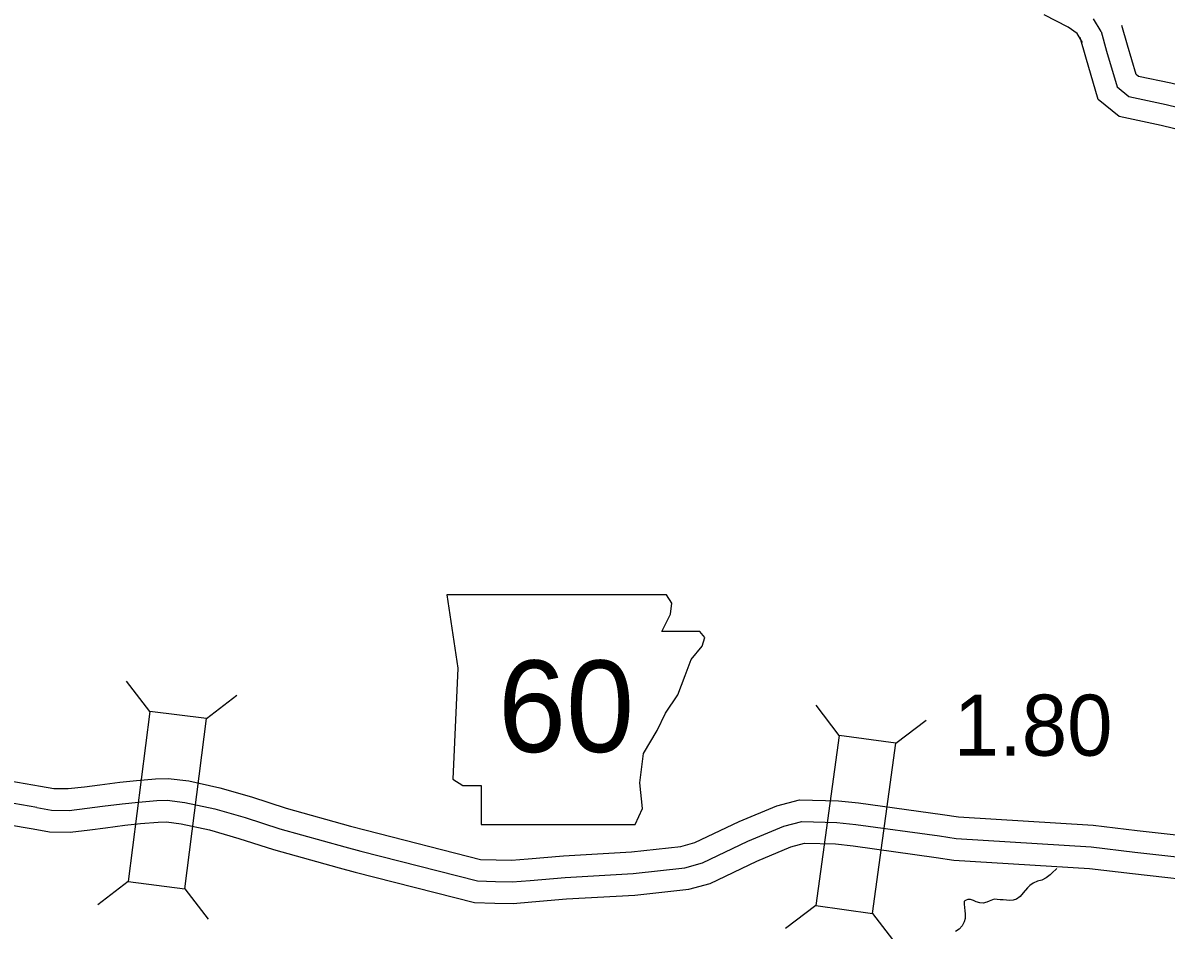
# Model space of a CAD drawing. Extents: x -83719 to 153526, y -11835 to 11446.
# Drawn here: x -2511.6 to -2247.8, y -714.3 to -505 of the extents above; entities that cross this region are included whole.
import ezdxf

# ---------------------------------------------------------------- set-up
doc = ezdxf.new("R2010")
doc.units = 0
for name, color, linetype in [('Level 10', 7, 'Continuous'), ('Level 20', 7, 'Continuous'), ('Level 21', 7, 'Continuous'), ('Level 58', 7, 'Continuous'), ('Level 59', 7, 'Continuous'), ('Level 9', 7, 'Continuous')]:
    doc.layers.add(name, color=color, linetype=linetype)

msp = doc.modelspace()

# ---------------------------------------------------------------- linework, layer by layer
at = {"layer": 'Level 10'}
for points in [[(-2267.06, -509.51), (-2268.32, -507.43), (-2270.35, -505.94), (-2275.89, -503.11)], [(-2135.16, -576.52), (-2141.29, -573.98), (-2181.87, -556.65), (-2184.87, -554.37), (-2191.3, -548.63), (-2202.4, -542.48), (-2211.06, -534.91), (-2216.36, -528), (-2222.14, -525.8), (-2230.15, -522.9), (-2246.67, -518.89), (-2254.14, -517.3), (-2254.7, -516.84), (-2256.69, -510.08), (-2257.97, -505.56)], [(-2138.99, -585.76), (-2145.17, -583.2), (-2186.94, -565.36), (-2191.24, -562.09), (-2197.12, -556.83), (-2208.18, -550.71), (-2218.38, -541.78), (-2222.56, -536.33), (-2225.62, -535.17), (-2233.04, -532.49), (-2248.89, -528.64), (-2258.59, -526.58), (-2263.42, -522.64), (-2266.3, -512.85), (-2267.59, -508.29)], [(-2728.32, -577.84), (-2728.29, -580.71), (-2727.84, -582.83), (-2720.37, -595.06), (-2719.66, -595.98), (-2718.27, -597.3), (-2689.7, -619.8), (-2686.51, -622.61), (-2684.68, -624.5), (-2683.87, -625.46), (-2658.55, -643.64), (-2631.11, -664.52), (-2627.02, -666.72), (-2625.87, -667.15), (-2609.49, -670.06), (-2587.64, -673.43), (-2562.55, -676.63), (-2560.66, -676.75), (-2547.94, -675.61), (-2544.34, -675.47), (-2519.99, -678.91), (-2507.5, -681.04)], [(-2737.85, -583.84), (-2737.27, -586.58), (-2728.62, -600.74), (-2727.11, -602.7), (-2724.81, -604.87), (-2696.1, -627.49), (-2693.42, -629.86), (-2692.09, -631.22), (-2690.7, -632.86), (-2664.5, -651.68), (-2636.54, -672.96), (-2631.17, -675.84), (-2628.54, -676.84), (-2611.12, -679.92), (-2589.03, -683.33), (-2563.53, -686.58), (-2560.55, -686.78), (-2547.3, -685.59), (-2544.85, -685.5), (-2521.53, -688.79), (-2509.19, -690.9)], [(-2507.47, -681.05), (-2504.44, -681.59), (-2501.14, -681.63), (-2497.37, -681.19), (-2493.81, -680.73), (-2489.19, -680.13), (-2485.34, -679.75), (-2480.94, -679.38), (-2478.02, -679.26), (-2473.3, -679.86), (-2466.08, -681.42), (-2458.78, -683.53), (-2450.82, -686.11), (-2435.93, -690.27), (-2432.35, -691.22), (-2405.93, -697.94), (-2402.37, -698.08), (-2398.8, -698.13), (-2394.93, -697.8), (-2386.81, -697.11), (-2371.15, -696.21), (-2359.74, -694.97), (-2356.48, -694.08), (-2346.31, -689.22), (-2337.57, -685.57), (-2332.38, -684.18), (-2323.37, -684.42), (-2318.71, -684.93), (-2299.36, -687.58), (-2295.66, -688.14), (-2264.57, -690.08), (-2254.41, -691.28), (-2235.83, -693.34)], [(-2509.22, -690.9), (-2505.39, -691.58), (-2500.62, -691.64), (-2496.14, -691.12), (-2492.52, -690.65), (-2488.04, -690.06), (-2484.44, -689.71), (-2480.32, -689.37), (-2478.45, -689.29), (-2475, -689.73), (-2468.53, -691.13), (-2461.71, -693.1), (-2453.71, -695.69), (-2438.56, -699.91), (-2434.87, -700.9), (-2407.36, -707.9), (-2402.63, -708.07), (-2398.46, -708.14), (-2394.08, -707.77), (-2386.1, -707.08), (-2370.32, -706.18), (-2357.87, -704.82), (-2352.98, -703.49), (-2342.22, -698.35), (-2334.34, -695.06), (-2331.19, -694.22), (-2324.05, -694.4), (-2319.94, -694.85), (-2300.79, -697.48), (-2296.72, -698.1), (-2265.47, -700.04), (-2255.55, -701.22), (-2236.53, -703.33)]]:
    msp.add_lwpolyline(points, dxfattribs=at)
at = {"layer": 'Level 20'}
for p, q in [((-2482.27, -663.8), (-2487.66, -656.84)), ((-2469.18, -665.47), (-2462.22, -660.08)), ((-2323.18, -669.38), (-2328.5, -662.37)), ((-2310.1, -671.17), (-2303.09, -665.85)), ((-2487.29, -703.08), (-2494.25, -708.46)), ((-2474.19, -704.75), (-2468.81, -711.71)), ((-2328.55, -708.61), (-2335.56, -713.93)), ((-2315.48, -710.4), (-2310.16, -717.41))]:
    msp.add_line(p, q, dxfattribs=at)
for points in [[(-2474.19, -704.75), (-2469.18, -665.47), (-2482.27, -663.8), (-2487.29, -703.08)], [(-2315.48, -710.4), (-2310.1, -671.17), (-2323.18, -669.38), (-2328.55, -708.61)]]:
    msp.add_lwpolyline(points, close=True, dxfattribs=at)
at = {"layer": 'Level 21'}
msp.add_lwpolyline([(-2413.73, -636.9), (-2411.19, -653.82), (-2412.32, -679.47), (-2410.06, -680.88), (-2405.83, -680.88), (-2405.83, -689.91), (-2370.3, -689.91), (-2368.61, -686.24), (-2369.17, -680.32), (-2368.33, -673.55), (-2365.23, -668.2), (-2363.25, -664.25), (-2360.43, -660.02), (-2358.74, -655.51), (-2357.33, -651.84), (-2354.79, -648.74), (-2354.23, -646.77), (-2355.36, -645.36), (-2364.1, -645.36), (-2362.13, -641.41), (-2361.84, -638.87), (-2363.01, -636.92)], close=True, dxfattribs=at)
at = {"layer": 'Level 59'}
for points in [[(-2262.78, -506.93), (-2264.55, -504)], [(-2262.78, -506.93), (-2261.49, -511.46), (-2259.06, -519.74), (-2256.37, -521.94), (-2247.78, -523.77), (-2231.59, -527.69), (-2223.88, -530.48), (-2219.46, -532.16), (-2214.72, -538.34), (-2205.29, -546.59), (-2194.21, -552.73), (-2188.05, -558.23), (-2184.41, -561), (-2143.23, -578.59), (-2137.08, -581.14)], [(-2508.35, -685.97), (-2520.76, -683.85)], [(-2508.35, -685.97), (-2504.92, -686.58), (-2500.88, -686.64), (-2496.76, -686.16), (-2493.17, -685.69), (-2488.61, -685.1), (-2484.89, -684.73), (-2480.63, -684.37), (-2478.23, -684.27), (-2474.15, -684.8), (-2467.3, -686.27), (-2460.24, -688.32), (-2452.27, -690.9), (-2437.24, -695.09), (-2433.61, -696.06), (-2406.64, -702.92), (-2402.5, -703.07), (-2398.63, -703.13), (-2394.51, -702.79), (-2386.45, -702.1), (-2370.74, -701.19), (-2358.8, -699.89), (-2354.73, -698.78), (-2344.26, -693.78), (-2335.96, -690.32), (-2331.78, -689.2), (-2323.71, -689.41), (-2319.33, -689.89), (-2300.08, -692.53), (-2296.19, -693.12), (-2265.02, -695.06), (-2254.98, -696.25), (-2236.18, -698.34)]]:
    msp.add_lwpolyline(points, dxfattribs=at)
at = {"layer": 'Level 9'}
for points in [[(-2273.11, -700.18), (-2273.94, -700.99), (-2274.53, -701.5), (-2275.46, -702.24), (-2276.42, -702.72), (-2277.42, -703), (-2278.41, -703.41), (-2279.24, -703.95), (-2279.74, -704.55), (-2280.76, -705.7), (-2281.42, -706.51), (-2282.31, -707.15), (-2283.04, -707.39), (-2283.91, -707.43), (-2284.61, -707.37), (-2285.34, -707.31), (-2286.04, -707.25), (-2287.41, -707.13), (-2288.61, -707.61), (-2289.11, -707.85), (-2290, -708.06), (-2290.74, -707.97), (-2291.61, -707.71), (-2292.21, -707.45), (-2292.88, -707.22), (-2293.51, -707.23), (-2293.91, -707.33), (-2294.21, -707.53), (-2294.34, -707.7), (-2294.34, -708.24), (-2294.29, -709.1), (-2294.19, -709.77), (-2294.11, -710.6), (-2294.1, -711.6), (-2294.33, -712.37), (-2294.82, -713.28), (-2295.51, -714.02), (-2296.37, -714.6)], [(-2272.94, -700.08), (-2273.11, -700.18)]]:
    msp.add_lwpolyline(points, dxfattribs=at)

# ---------------------------------------------------------------- texts
at = {"layer": 'Level 21'}
msp.add_text('60', height=21.12, dxfattribs=at).set_placement((-2401.93, -673.18))
at = {"layer": 'Level 58'}
msp.add_text('1.80', height=14.08, dxfattribs=at).set_placement((-2296.77, -674.03))

doc.saveas('drawing.dxf')
